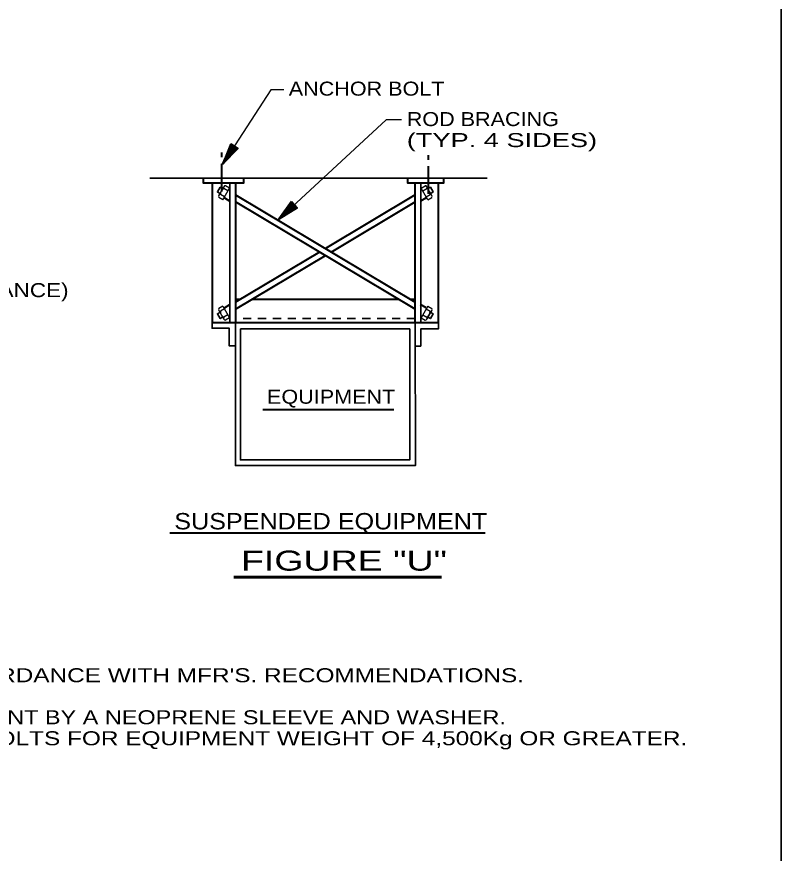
# Model space of a CAD drawing. Extents: x 55 to 190, y 198 to 264.
# Drawn here: x 126.14 to 139.99, y 231.1 to 246.26 of the extents above; entities that cross this region are included whole.
import ezdxf
from ezdxf.enums import TextEntityAlignment as Align

# ---------------------------------------------------------------- set-up
doc = ezdxf.new("R2010")
doc.units = 0
doc.header["$LTSCALE"] = 0.1
doc.linetypes.add('DOT_DASHED', pattern=[7.7, 5, -1.2, 0.3, -1.2])
doc.linetypes.add('SHORT_DASHED', pattern=[2.7, 1.5, -1.2])
doc.layers.add('2', color=7, linetype='Continuous', lineweight=40)

msp = doc.modelspace()

# ---------------------------------------------------------------- linework, layer by layer
at = {"layer": '2', "lineweight": 35}
for p, q in [((139.9927, 256.6525), (139.9927, 199.6512)), ((128.5558, 243.3385), (134.664, 243.3385)), ((130.0031, 243.2501), (130.0031, 240.7149)), ((133.4604, 240.7143), (133.4604, 243.2501))]:
    msp.add_line(p, q, dxfattribs=at)
at = {"layer": '2'}
for p, q in [((129.8742, 243.5972), (130.0346, 243.9489)), ((129.8742, 243.5972), (130.0528, 243.9378)), ((129.8742, 243.5972), (130.0668, 243.9282)), ((130.0819, 243.9187), (129.8742, 243.5972)), ((129.8742, 243.5972), (130.0978, 243.9079)), ((129.8742, 243.5972), (130.1293, 243.8877)), ((129.6827, 243.2501), (129.6827, 240.7149)), ((130.1026, 243.2501), (130.1026, 240.7149)), ((133.3609, 240.7143), (133.3609, 243.2501)), ((133.7808, 240.7143), (133.7808, 243.2501)), ((129.906, 242.9789), (130.0039, 242.9204)), ((130.1026, 243.0329), (133.3609, 241.0866)), ((133.3625, 243.0329), (131.7326, 242.0592)), ((133.5572, 242.9789), (133.4593, 242.9204)), ((133.3609, 240.9599), (130.1026, 242.9059)), ((130.8902, 242.5958), (131.1326, 242.8972)), ((130.8902, 242.5958), (131.1474, 242.8818)), ((130.8902, 242.5958), (131.1585, 242.8689)), ((131.1709, 242.8559), (130.8902, 242.5958)), ((130.8902, 242.5958), (131.1836, 242.8416)), ((131.8388, 241.996), (133.3625, 242.9059)), ((130.8902, 242.5958), (131.209, 242.8143)), ((131.6266, 241.996), (130.1041, 241.0866)), ((130.1041, 240.9599), (131.7326, 241.9325)), ((129.906, 240.9861), (130.0039, 241.0445)), ((130.1846, 241.1348), (130.1026, 241.1348)), ((133.0662, 241.1348), (130.3952, 241.1348)), ((133.3609, 241.1348), (133.2749, 241.1348)), ((133.5572, 240.9861), (133.4593, 241.0445)), ((133.7808, 240.7149), (129.6827, 240.7149)), ((130.6016, 239.1438), (132.9741, 239.1438)), ((128.9135, 236.9065), (134.6282, 236.9065))]:
    msp.add_line(p, q, dxfattribs=at)
at = {"layer": '2', "linetype": 'DOT_DASHED'}
for p, q in [((129.8594, 243.0967), (129.8594, 243.8015)), ((133.5996, 243.0525), (133.5996, 243.7573))]:
    msp.add_line(p, q, dxfattribs=at)
at = {"layer": '2', "lineweight": 25}
for p, q in [((129.8015, 243.0255), (129.8925, 243.1829)), ((129.8755, 242.9474), (129.9967, 243.1575)), ((129.9666, 243.1051), (129.8933, 243.1475)), ((129.9967, 243.1575), (129.924, 243.1996)), ((133.4665, 243.1575), (133.5392, 243.1996)), ((133.5876, 242.9474), (133.4665, 243.1575)), ((133.4966, 243.1051), (133.5699, 243.1475)), ((133.6617, 243.0255), (133.5707, 243.1829)), ((129.8755, 242.9474), (129.8023, 242.9898)), ((129.9054, 242.9996), (129.8322, 243.0419)), ((133.5577, 242.9996), (133.631, 243.0419)), ((133.5876, 242.9474), (133.6609, 242.9898)), ((129.8755, 241.0176), (129.8023, 240.9752)), ((129.8755, 241.0176), (129.9967, 240.8075)), ((133.5876, 241.0176), (133.4665, 240.8075)), ((133.5876, 241.0176), (133.6609, 240.9752)), ((129.8015, 240.9395), (129.8925, 240.7821)), ((129.9054, 240.9654), (129.8322, 240.9231)), ((129.9666, 240.8599), (129.8933, 240.8175)), ((133.4966, 240.8599), (133.5699, 240.8175)), ((133.5577, 240.9654), (133.631, 240.9231)), ((133.6617, 240.9395), (133.5707, 240.7821)), ((129.9967, 240.8075), (129.924, 240.7654)), ((133.4665, 240.8075), (133.5392, 240.7654))]:
    msp.add_line(p, q, dxfattribs=at)
at = {"layer": '2', "linetype": 'SHORT_DASHED', "lineweight": 35}
msp.add_line((133.3609, 240.7919), (130.1026, 240.7919), dxfattribs=at)
at = {"layer": '2', "lineweight": 60}
msp.add_line((130.0729, 236.1011), (133.8387, 236.1011), dxfattribs=at)
at = {"layer": '2', "lineweight": 25}
for points in [[(130.9786, 244.9371), (130.7428, 244.9371), (129.8742, 243.5972)], [(133.1135, 244.3923), (132.8339, 244.3923), (130.8902, 242.5958)]]:
    msp.add_lwpolyline(points, dxfattribs=at)
at = {"layer": '2'}
for points in [[(130.0181, 243.9597), (130.1465, 243.8761), (129.8742, 243.5972)], [(130.0181, 243.9597), (129.8742, 243.5972), (130.1139, 243.8978)], [(129.517, 243.3385), (129.517, 243.2501), (130.2573, 243.2501), (130.2573, 243.3385)], [(133.2188, 243.3385), (133.2188, 243.2501), (133.8816, 243.2501), (133.8816, 243.3385)], [(131.1194, 242.9114), (131.2231, 242.7987), (130.8902, 242.5958)], [(131.1194, 242.9114), (130.8902, 242.5958), (131.1969, 242.8278)]]:
    msp.add_lwpolyline(points, dxfattribs=at)
at = {"layer": '2', "lineweight": 35}
for points in [[(129.8713, 243.1477), (129.8274, 243.1731), (129.7776, 243.0869), (129.8216, 243.0615)], [(133.5919, 243.1477), (133.6358, 243.1731), (133.6855, 243.0869), (133.6416, 243.0615)], [(129.8713, 240.8173), (129.8274, 240.7919), (129.7776, 240.8781), (129.8216, 240.9035)], [(133.5919, 240.8173), (133.6358, 240.7919), (133.6855, 240.8781), (133.6416, 240.9035)], [(129.6798, 240.7162), (129.6798, 240.6165), (129.9914, 240.6165), (129.9914, 240.2968), (130.1026, 240.2968)], [(130.1026, 240.7149), (130.1026, 238.1259), (133.3641, 238.1259), (133.3609, 240.7143)], [(133.3609, 240.2915), (133.4606, 240.2915), (133.4606, 240.603), (133.7803, 240.603), (133.7803, 240.7143)]]:
    msp.add_lwpolyline(points, dxfattribs=at)
msp.add_lwpolyline([(130.1928, 240.6045), (130.1928, 238.2278), (133.2619, 238.2278), (133.2619, 240.6045)], close=True, dxfattribs=at)
at = {"layer": '2', "lineweight": 25}
for centre, radius, start, end in [((129.944, 243.0478), 0.1121, 117.00616, 182.94297), ((129.922, 243.1656), 0.0339, 86.78269, 211.8391), ((133.5411, 243.1656), 0.0339, 328.1609, 93.21731), ((133.5192, 243.0478), 0.1121, 357.05703, 62.99384), ((129.8308, 243.0081), 0.0339, 87.8877, 212.03419), ((133.6323, 243.0081), 0.0339, 327.96581, 92.1123), ((129.8308, 240.9568), 0.0339, 147.96581, 272.1123), ((129.944, 240.9172), 0.1121, 177.05703, 242.99384), ((133.5192, 240.9172), 0.1121, 297.00616, 2.94297), ((133.6323, 240.9568), 0.0339, 267.8877, 32.03419), ((129.922, 240.7994), 0.0339, 148.1609, 273.21731), ((133.5411, 240.7994), 0.0339, 266.78269, 31.8391)]:
    msp.add_arc(centre, radius, start, end, dxfattribs=at)

# ---------------------------------------------------------------- texts
at = {"layer": '2'}
for s, width, p in [('ANCHOR BOLT', 1.15, (131.0699, 244.8334)), ('ROD BRACING', 1.15, (133.208, 244.2815)), ('(TYP. 4 SIDES)', 1.45, (133.208, 243.9005)), ('GAP(CLEARANCE)', 1.2, (123.4571, 241.1803)), ('1. CLEARANCES AT SIDES FOR SPRING MOUNTED EQUIPMENT AS IN FIG. "R" & "S", SHALL BE IN ACCORDANCE WITH MFR\'S. RECOMMENDATIONS.', 1.3, (103.733, 234.1984)), ('3. IF EQUIPMENT IS MOUNTED ON NEOPRENE PADS, ANCHOR BOLTS SHALL BE ISOLATED FROM EQUIPMENT BY A NEOPRENE SLEEVE AND WASHER.', 1.25, (103.7692, 233.4363)), ('4. PROVIDE A MINIMUM OF (4) 13mm ANCHOR BOLTS FOR EQUIPMENT UP TO 4,500 Kg AND (4) 19mm BOLTS FOR EQUIPMENT WEIGHT OF 4,500Kg OR GREATER.', 1.3, (103.7692, 233.0554))]:
    msp.add_text(s, height=0.254, dxfattribs=dict(at, width=width)).set_placement(p)
for s, height, width, p in [('EQUIPMENT', 0.254, 1.15, (131.8374, 239.2475)), ('SUSPENDED EQUIPMENT', 0.2963, 1.15, (131.8311, 236.9697)), ('FIGURE "U"', 0.3633, 1.4, (132.0696, 236.2212))]:
    msp.add_text(s, height=height, dxfattribs=dict(at, width=width)).set_placement(p, align=Align.CENTER)

doc.saveas('drawing.dxf')
